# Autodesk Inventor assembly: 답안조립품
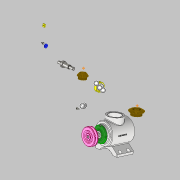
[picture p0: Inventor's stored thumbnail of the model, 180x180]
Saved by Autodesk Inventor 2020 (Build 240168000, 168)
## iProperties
Created: 2023-12
Part Number: 답안조립품
Document SubType Name: Assembly
Designer: 1강의실14
Author: 1강의실14
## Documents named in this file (17)
- C:\Users\1강의실14\Desktop\731203V1012\답안조립품.iam
- C:\Users\1강의실14\Desktop\731203V1012\본체.ipt
- C:\Users\1강의실14\Desktop\731203V1012\V-벨트풀리.ipt
- C:\Users\1강의실14\Desktop\731203V1012\메인 베벨기어.ipt
- C:\Users\1강의실14\Desktop\731203V1012\메인 축.ipt
- 메인 축.ipt
- C:\Users\1강의실14\Desktop\731203V1012\베어링 6203.ipt
- C:\Users\1강의실14\Desktop\731203V1012\볼트 M4 x 10.ipt
- C:\Users\1강의실14\Desktop\731203V1012\서브 베벨기어.ipt
- C:\Users\1강의실14\Desktop\731203V1012\서브 축.ipt
- 서브 축.ipt
- C:\Users\1강의실14\Desktop\731203V1012\오일실 17 x 32 x 8.ipt
- C:\Users\1강의실14\Desktop\731203V1012\와셔 4 x 16.ipt
- C:\Users\1강의실14\Desktop\731203V1012\육각볼트 M4 x 8.ipt
- C:\Users\1강의실14\Desktop\731203V1012\키 4 x 4 x 14.ipt
- C:\Users\1강의실14\Desktop\731203V1012\키 5 x 5 x 14.ipt
- C:\Users\1강의실14\Desktop\731203V1012\커버.ipt
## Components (1 placed, 1 different names)
1. V-벨트풀리:1
